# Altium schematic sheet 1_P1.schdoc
size 309 x 223 mm; Symbol: Sheet-Symbol_A4; Device: Sheet-Symbol_A4; @Page Name: P1; @Create Date: 2023-08-18; @Page Count: 1; @Page No: 1; @Project Name: 【废土科技】带抬头显示及监控器的多功能观测仪_V3; @Schematic Name: 测距传感器及CAM板; @Update Date: 2023-08-20; Company: 嘉立创EDA; Drawed: Kevin_Wuu; Page Size: A4; Version: V1.0
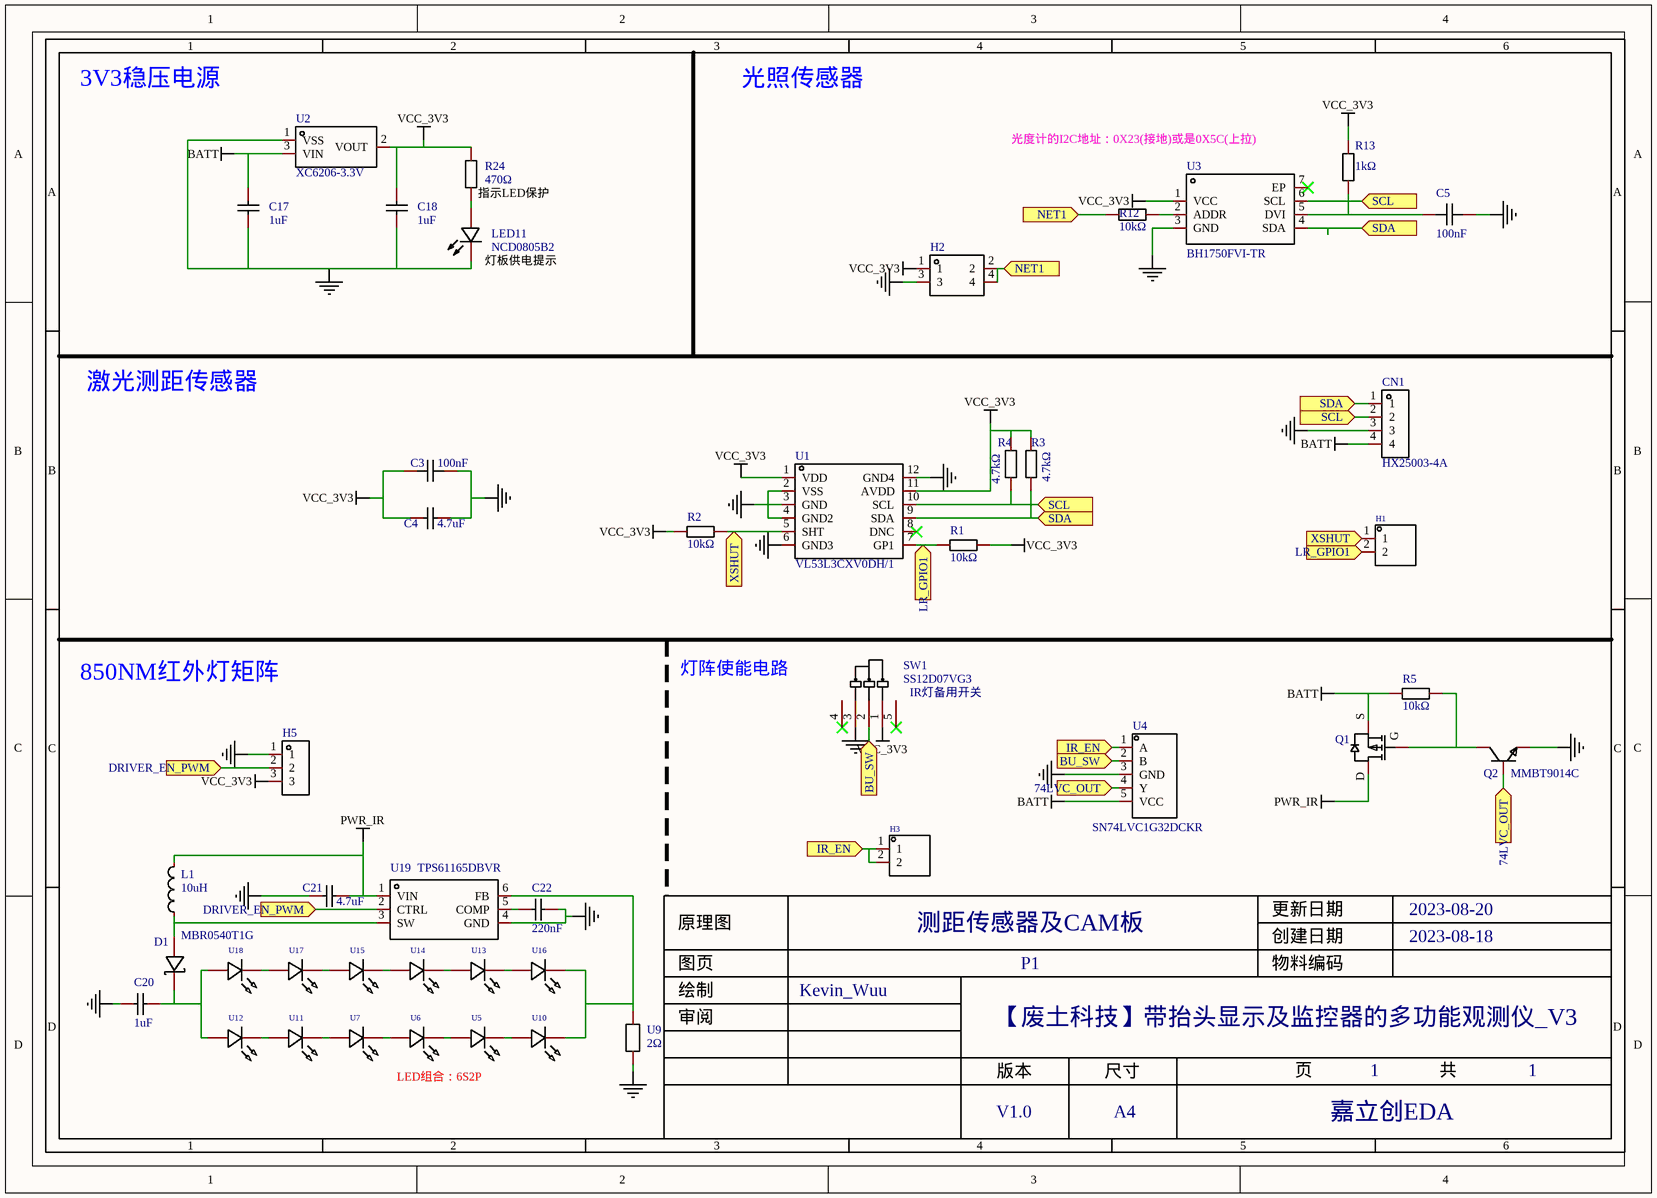
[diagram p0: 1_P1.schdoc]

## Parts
C3  100nF  [C0603]
C4  4.7uF  [C0805]
C5  100nF  [C0603]
C17  1uF  [C0805]
C18  1uF  [C0805]
C20  1uF  [C0603]
C21  4.7uF  [C0805]
C22  220nF  [C0603]
CN1  HX25003-4A  [CONN-TH_4P-P2.50_HX25003-4A]
D1  MBR0540T1G  [SOD-123_L2.8-W1.8-LS3.7-RD]
H1  HDR-M_2.54_1x2P  [HDR-TH_2P-P2.54-V-M-1]  (value not drawn)
H2  HDR-M_2.54_2x2  [HDR-TH_4P-P2.54-V-M-R2-C2-S2.54-1]  (value not drawn)
H3  HDR-M_2.54_1x2P  [HDR-TH_2P-P2.54-V-M-1]  (value not drawn)
H5  HDR-M_2.54_1x3P  [HDR-TH_3P-P2.54-V-M]  (value not drawn)
L1  10uH  [IND-SMD_L4.4-W4.2]
LED11  NCD0805B2  [LED0805-R-RD]
Q1  AO3401A  [SOT-23_L2.9-W1.3-P1.90-LS2.4-BR]  (value not drawn)
Q2  MMBT9014C  [SOT-23-3_L2.9-W1.3-P1.90-LS2.4-BR]
R1  10kΩ  [R0805]
R2  10kΩ  [R0805]
R3  4.7kΩ  [R0805]
R4  4.7kΩ  [R0805]
R5  10kΩ  [R0805]
R12  10kΩ  [R0805]
R13  1kΩ  [R0805]
R24  470Ω  [R0603]
SW1  SS12D07VG3  [SW-TH_SS12D07VG3]
U1  VL53L3CXV0DH/1  [OPTO-SMD_12P_VL53L3CXV0DH]
U2  XC6206-3.3V  [SSOT-3_L2.9-W1.6-P0.95-LS2.8-BR]
U3  BH1750FVI-TR  [WSOF-6_L2.6-W1.6-P0.50-TL-EP]
U4  SN74LVC1G32DCKR  [SOT-353_L2.1-W1.3-P0.65-LS2.3-BR]
U5  vsly5940  [LED-TH_BD5.8-P2.54-L-RD]  (value not drawn)
U6  vsly5940  [LED-TH_BD5.8-P2.54-L-RD]  (value not drawn)
U7  vsly5940  [LED-TH_BD5.8-P2.54-L-RD]  (value not drawn)
U9  2Ω  [R1206]
U10  vsly5940  [LED-TH_BD5.8-P2.54-L-RD]  (value not drawn)
U11  vsly5940  [LED-TH_BD5.8-P2.54-L-RD]  (value not drawn)
U12  vsly5940  [LED-TH_BD5.8-P2.54-L-RD]  (value not drawn)
U13  vsly5940  [LED-TH_BD5.8-P2.54-L-RD]  (value not drawn)
U14  vsly5940  [LED-TH_BD5.8-P2.54-L-RD]  (value not drawn)
U15  vsly5940  [LED-TH_BD5.8-P2.54-L-RD]  (value not drawn)
U16  vsly5940  [LED-TH_BD5.8-P2.54-L-RD]  (value not drawn)
U17  vsly5940  [LED-TH_BD5.8-P2.54-L-RD]  (value not drawn)
U18  vsly5940  [LED-TH_BD5.8-P2.54-L-RD]  (value not drawn)
U19  TPS61165DBVR  [SOT-23-6_L2.9-W1.6-P0.95-LS2.8-BR]

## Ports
74LVC_OUT (in), BU_SW (in), DRIVER_EN_PWM (in), IR_EN (in), LR_GPIO1 (in), NET1 (in), SCL (in), SDA (in), XSHUT (in)

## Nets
BATT: C17.1 CN1.4 Q1.2(S) R5.1 U2.3(VIN) U4.5(VCC)
NetC3_2: C3.2 C4.2 C5.2 C17.2 C18.2 C20.1 C21.2 C22.2 CN1.3 H2.3 H5.1 LED11.2(-) Q2.2(E) SW1.3 U1.2(VSS) U1.3(GND) U1.4(GND2) U1.6(GND3) U1.12(GND4) U2.1(VSS) U3.3(GND) U4.3(GND) U9.1 U19.4(GND)
PWR_IR: C21.1 L1.2 Q1.3(D) U19.1(VIN)
VCC_3V3: C3.1 C4.1 C18.1 H2.1 H5.3 R1.1 R2.1 R3.2 R4.2 R13.2 R24.2 SW1.1 U1.1(VDD) U1.11(AVDD) U2.2(VOUT) U3.1(VCC)
74LVC_OUT: Q2.1(B) U4.4(Y) ; port 74LVC_OUT
BU_SW: SW1.2 U4.2(B) ; port BU_SW
DRIVER_EN_PWM: H5.2 U19.2(CTRL) ; port DRIVER_EN_PWM
IR_EN: H3.1 H3.2 U4.1(A) ; port IR_EN
LR_GPIO1: H1.2 R1.2 U1.7(GP1) ; port LR_GPIO1
NET1: H2.2 H2.4 R12.2 ; port NET1
SCL: CN1.2 R4.1 U1.10(SCL) U3.6(SCL) ; port SCL
SDA: CN1.1 R3.1 U1.9(SDA) U3.4(SDA) ; port SDA
XSHUT: H1.1 R2.2 U1.5(SHT) ; port XSHUT
NetC5_1: C5.1 R13.1 U3.5(DVI)
NetC20_2: C20.2 D1.1(K) U12.2(+) U18.2(+)
NetC22_1: C22.1 U19.5(COMP)
NetD1_2: D1.2(A) L1.1 U19.3(SW)
NetLED11_1: LED11.1(+) R24.1
NetQ1_1: Q1.1(G) Q2.3(C) R5.2
NetR12_1: R12.1 U3.2(ADDR)
NetU5_1: U5.1(-) U10.2(+)
NetU5_2: U5.2(+) U6.1(-)
NetU6_2: U6.2(+) U7.1(-)
NetU7_2: U7.2(+) U11.1(-)
NetU9_2: U9.2 U10.1(-) U16.1(-) U19.6(FB)
NetU11_2: U11.2(+) U12.1(-)
NetU13_1: U13.1(-) U16.2(+)
NetU13_2: U13.2(+) U14.1(-)
NetU14_2: U14.2(+) U15.1(-)
NetU15_2: U15.2(+) U17.1(-)
NetU17_2: U17.2(+) U18.1(-)

Not connected (* = marked no-connect by the designer): SW1 4* 5*; U1 8(DNC)*; U3 7(EP)*

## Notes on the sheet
- 3V3稳压电源
- 光照传感器
- (near U3) 光度计的I2C地址：0X23(接地)或是0X5C(上拉)
- (near R24) 指示LED保护
- (near LED11) 灯板供电提示
- 激光测距传感器
- 850NM红外灯矩阵
- 灯阵使能电路
- (near Q1) S
- (near Q1) G
- (near Q1) D
- LED组合：6S2P

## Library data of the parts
C3 C5 = CC0603KRX7R9BB104: 容值:100nF;精度:±10%;额定电压:50V;材质(温度系数):X7R;; Manufacturer: YAGEO(国巨); Add into BOM: yes; Tolerance: ±10%; Voltage Rated: 50V; Temperature Coefficient: X7R
C4 C21 = CL21A475KAQNNNE: 容值:4.7uF;精度:±10%;额定电压:25V;材质(温度系数):X5R;; Manufacturer: SAMSUNG(三星); Add into BOM: yes; Tolerance: ±10%; Voltage Rated: 25V; Temperature Coefficient: X5R
C17 C18 = CL21B105KBFNNNE: 容值:1uF;精度:±10%;额定电压:50V;材质(温度系数):X7R;; Manufacturer: SAMSUNG(三星); Add into BOM: yes; Tolerance: ±10%; Voltage Rated: 50V; Temperature Coefficient: X7R
C20 = CL10A105KB8NNNC: 容值:1uF;精度:±10%;额定电压:50V;材质(温度系数):X5R;; Manufacturer: SAMSUNG(三星); Add into BOM: yes; Tolerance: ±10%; Voltage Rated: 50V; Temperature Coefficient: X5R
C22 = CL10B224KA8NNNC: 容值:220nF;精度:±10%;额定电压:25V;材质(温度系数):X7R;; Manufacturer: SAMSUNG(三星); Add into BOM: yes; Tolerance: ±10%; Voltage Rated: 25V; Temperature Coefficient: X7R
CN1 = HX25003-4A: 参考系列:XH;间距:2.5mm;插针结构:1x4P;排数:1;每排PIN数:4;行距:-;公母:公型插针;安装方式:直插;额定电流:-;工作温度范围:-;; Manufacturer: HX(红星); Add into BOM: yes; Reference Series: XH; Pitch: 2.5mm; Pins Structure: 1x4P; Number of PINs Per Row: 4; Gender: 公型插针
D1 = MBR0540T1G: 直流反向耐压(Vr):40V;平均整流电流(Io):500mA;正向压降(Vf):510mV@500mA;; Manufacturer: onsemi(安森美); Add into BOM: yes; Reverse Voltage (Vr): 40V; Average Rectified Current (Io): 500mA
H1 H3 = HDR-M_2.54_1x2P: Manufacturer: Ckmtw(灿科盟); Manufacturer Part: B-2100S02P-A110; Symbol: 210S-1*2P L=11.6MMGold-plated black; Convert to PCB: yes
H2 = HDR-M_2.54_2x2: Symbol: HDR-M-2.54_2x2; Convert to PCB: yes; Check: false
H5 = HDR-M_2.54_1x3P: Symbol: PZ254V-11-03P_C2937625; Convert to PCB: yes
L1 = MWSA0402S-100MT: 类型:-;电感值:10uH;精度:±20%;额定电流:1.6A;饱和电流(Isat):2A;; Manufacturer: Sunlord(顺络); Add into BOM: yes; Tolerance: ±20%; Rated Current: 1.6A; Saturation Current (Isat): 2A; DC Resistance (DCR): 282mΩ
LED11 = NCD0805B2: 发光颜色:蓝灯;; Manufacturer: 国星光电; Symbol: FC-A2012BK-470H2; Add into BOM: yes; Emitted Color: 蓝灯
Q1 = AO3401A_C15127: 类型:P沟道;漏源电压(Vdss):30V;连续漏极电流(Id):4A;功率(Pd):1.4W;导通电阻(RDS(on)@Vgs,Id):44mΩ@10V,4.3A;; Manufacturer: AOS; Add into BOM: yes; Type: P沟道; Drain Source Voltage (Vdss): 30V; Continuous Drain Current (Id): 4A; Power Dissipation (Pd): 1.4W; Gate Threshold Voltage (Vgs(th)@Id): 1.3V@250uA
Q2 = MMBT9014C: 晶体管类型:NPN;集射极击穿电压(Vceo):45V;集电极电流(Ic):100mA;功率(Pd):200mW;直流电流增益(hFE@Ic,Vce):200@1mA,5V;; Manufacturer: ST(先科); Add into BOM: yes; Transistor Type: NPN; Collector-Emitter Breakdown Voltage (Vceo): 45V; Collector Current (Ic): 100mA; Power Dissipation (Pd): 200mW; Collector Cut-Off Current (Icbo): 50nA; Collector-Emitter Saturation Voltage (VCE(sat)@Ic,Ib): 250mV@100mA,10mA; Transition Frequency (fT): 100MHz
R1 R2 R5 R12 = RMCF0805FT10K0: 电阻类型:厚膜电阻;阻值:10kΩ;精度:±1%;功率:125mW;; Manufacturer: SEI(Stackpole Electronics Inc.); Add into BOM: yes; Tolerance: ±1%; Power(Watts): 125mW; Temperature Coefficient: ±100ppm/℃; Overload Voltage (Max): 150V
R3 R4 = 0805W8F4701T5E: 电阻类型:厚膜电阻;阻值:4.7kΩ;精度:±1%;功率:125mW;; Manufacturer: UNI-ROYAL(厚声); Add into BOM: yes; Tolerance: ±1%; Power(Watts): 125mW; Temperature Coefficient: ±100ppm/℃; Overload Voltage (Max): 150V
R13 = 0805W8F1001T5E: 电阻类型:厚膜电阻;阻值:1kΩ;精度:±1%;功率:125mW;; Manufacturer: UNI-ROYAL(厚声); Add into BOM: yes; Tolerance: ±1%; Power(Watts): 125mW; Temperature Coefficient: ±100ppm/℃; Overload Voltage (Max): 150V
R24 = 0603WAF4700T5E: 电阻类型:厚膜电阻;阻值:470Ω;精度:±1%;功率:100mW;; Manufacturer: UNI-ROYAL(厚声); Add into BOM: yes; Tolerance: ±1%; Power(Watts): 100mW; Temperature Coefficient: ±100ppm/℃; Overload Voltage (Max): 75V
SW1 = SS12D07VG3: Manufacturer: SHOU HAN(首韩); Add into BOM: yes; Check: false
U1 = VL53L3CXV0DH/1: Manufacturer: ST(意法半导体); Add into BOM: yes
U2 = XC6206-3.3V: 输出类型:固定;输出极性:正;最大输入电压:6V;输出电压:3.3V;输出电流:250mA;; Manufacturer: YONGYUTAI(永裕泰); Add into BOM: yes; Output Type: 固定; Output Polarity: 正; Number of Outputs: 1; Maximum Input Voltage: 6V; Output Voltage: 3.3V; Output Current: 250mA
U3 = BH1750FVI-TR: 数字16-bit I2C串行输出，环境光传感器，工作电压：2.4V~3.6V; Manufacturer: ROHM(罗姆); Add into BOM: yes
U4 = SN74LVC1G32DCKR: 逻辑电路的归属系列:74LVC;逻辑类型:或门;通道数:1;每通道输入数:2;电源电压:1.65V~5.5V;静态电流(最大值):10uA;; Manufacturer: TI(德州仪器); Add into BOM: yes; Logic Type: 或门; number of channels: 1; Number of inputs per channel: 2; Quiescent Current (Max): 10uA; Max Propagation Delay @ V, Max CL: 4ns@5V,50pF; Low Level Output Current: 32mA; Logical Level - High: 1.7V~2V; Logical Level - low: 0.7V~0.8V
U5-U7 U10-U18 = vsly5940: 辐射强度:-;; Manufacturer: VISHAY(威世); Add into BOM: yes
U9 = HoLTT1206-1/4W-2R-1%: 阻值:2Ω;功率:250mW;; Manufacturer: Milliohm(毫欧); Add into BOM: yes; Power(Watts): 250mW
U19 = TPS61165DBVR: TPS61165 采用 2mm x 2mm QFN 封装的白光 LED 驱动器; Manufacturer: TI(德州仪器); Add into BOM: yes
